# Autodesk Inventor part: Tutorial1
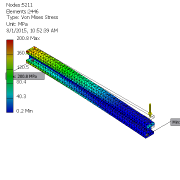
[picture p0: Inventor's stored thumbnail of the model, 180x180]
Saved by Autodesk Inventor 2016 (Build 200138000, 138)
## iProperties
Created: 2013-01
Part Number: Tutorial1
Material: Steel, Alloy
Document SubType Name: Modeling
Designer: CADCIM
Density: 7.85 g/cm^3
Appearance: Semi-Polished
Mass: 647.625 g
Surface Area: 365.5 cm^2
Volume: 82.5 cm^3
Author: CADCIM
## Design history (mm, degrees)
sketch "Sketch1"
  geometry: L1 (10, -13)-(-10, -13); L2 (-10, -13)-(-10, -8); L3 (-10, -8)-(-2.5, -8); L4 (-2.5, -8)-(-2.5, 7); L5 (-2.5, 7)-(-10, 7); L6 (-10, 7)-(-10, 12); L7 (-10, 12)-(10, 12); L8 (10, 12)-(10, 7); L9 (10, 7)-(2.5, 7); L10 (2.5, 7)-(2.5, -8); L11 (2.5, -8)-(10, -8); L12 (10, -8)-(10, -13); 1 further point
  constraints: 24 end point, 9 parallel, 1 collinear, 1 perpendicular
  dimensions: "d0" = 20 distance of L1.start L1.end; "d1" = 5 distance of L1.end L2.end; "d2" = 7.5 distance of L2.end L3.end; "d3" = 5 distance of L5.end L6.end; "d4" = 7.5 distance of L8.end L9.end; "d7" = 15 distance of L3.end L4.end
extrude "Extrusion1" new body sketch "Sketch1" distance "d5" = 300; taper "d6" = 0 deg
body "Solid1"
other parameters: "sa_0" = 0, "sa_1" = 0, "sa_2" = -1000000, "sa_3" = 0, "sa_4" = 0, "sa_5" = -1000000, "sa_6" = 0, "sa_7" = 0, "sa_8" = -1000000
